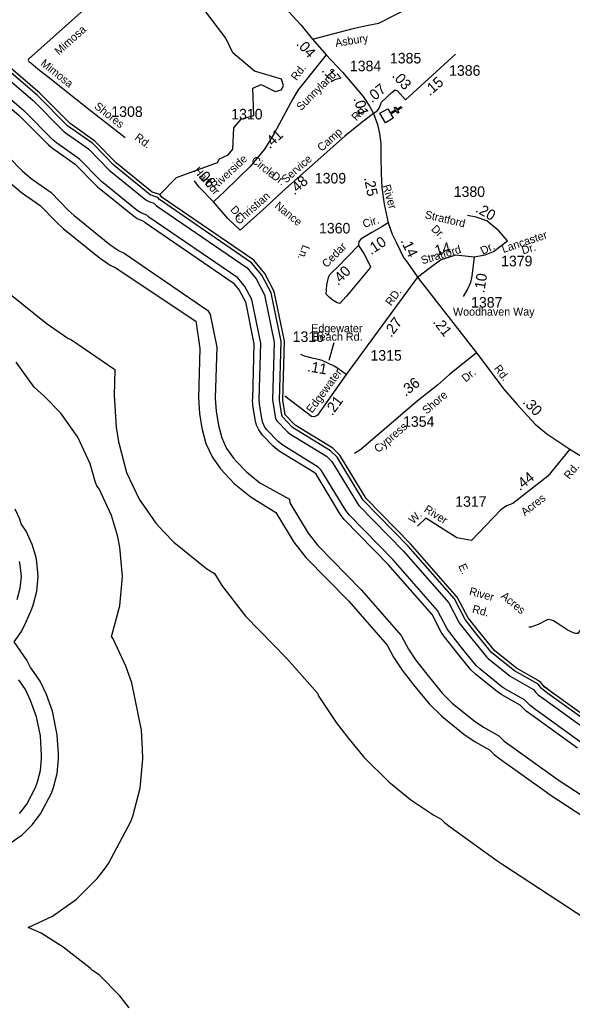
# Model space of a CAD drawing. Extents: x 2532689 to 2764727, y 536648 to 732970.
# Drawn here: x 2589422 to 2595978, y 639225 to 650929 of the extents above; entities that cross this region are included whole.
import ezdxf

# ---------------------------------------------------------------- set-up
doc = ezdxf.new("R2010")
doc.units = 0
for name, color, linetype in [('Exist Cultural Church CELL', 7, 'Continuous'), ('Exist Hydrographic Bay Label', 7, 'Continuous'), ('Exist Hydrographic Buffer Line', 7, 'Continuous'), ('Exist Hydrographic Creek Single Shore', 7, 'Continuous'), ('Exist Hydrographic River Shore', 7, 'Continuous'), ('Exist Road Primary NC Attributed', 7, 'Continuous'), ('Exist Road Primary NC Label', 7, 'Continuous'), ('Exist Road Primary NC Mileage Hundredths English Label', 7, 'Continuous'), ('Exist Road Secondary Mileage Hundredths English Label', 7, 'Continuous'), ('Exist Road Secondary Type 51 Attributed', 7, 'Continuous'), ('Exist Road Secondary Type 51 Label', 7, 'Continuous'), ('Exist Road Secondary Type 51 Number Label', 7, 'Continuous')]:
    doc.layers.add(name, color=color, linetype=linetype)

msp = doc.modelspace()

# ---------------------------------------------------------------- linework, layer by layer
at = {"layer": 'Exist Cultural Church CELL'}
msp.add_lwpolyline([(2593788, 649874), (2593816, 649824), (2593882, 649862), (2593866, 649890), (2593880, 649898), (2593896, 649870), (2593948, 649900), (2593956, 649886), (2593904, 649856), (2593920, 649828), (2593906, 649820), (2593890, 649848), (2593824, 649810), (2593853, 649760), (2593760, 649707), (2593695, 649821)], close=True, dxfattribs=at)
at = {"layer": 'Exist Hydrographic Bay Label'}
msp.add_line((2595711, 642968), (2595643, 643018), dxfattribs=at)
at = {"layer": 'Exist Hydrographic Buffer Line'}
for points in [[(2592502, 646416), (2592522, 647112), (2592404, 647691), (2592295, 647898), (2592173, 648046), (2591079, 648796), (2591061, 648821), (2590968, 648853), (2590541, 649200), (2590288, 649460), (2589990, 649670), (2589634, 650029), (2588885, 650670), (2588337, 650929), (2588091, 651115), (2587966, 651291)], [(2587714, 651088), (2587833, 650926), (2587908, 650850), (2588145, 650673), (2588207, 650635), (2588710, 650399), (2589416, 649794), (2589763, 649445), (2589812, 649404), (2590080, 649215), (2590312, 648977), (2590343, 648948), (2590767, 648605), (2590814, 648572), (2590870, 648546), (2590892, 648539), (2590909, 648523), (2591955, 647808), (2592027, 647720), (2592099, 647583), (2592201, 647084), (2592182, 646426)], [(2587898, 650973), (2587955, 650914), (2588192, 650737), (2588241, 650707), (2588754, 650467), (2589471, 649853)], [(2588842, 650602), (2589580, 649970), (2589933, 649614), (2589950, 649600), (2590236, 649398), (2590483, 649144), (2590918, 648791), (2590953, 648771), (2591012, 648752), (2591044, 648721), (2592119, 647987), (2592228, 647854), (2592327, 647664), (2592441, 647105), (2592422, 646419), (2592423, 646396), (2592451, 646223), (2592457, 646201), (2592466, 646183), (2592478, 646165), (2592602, 646036), (2592626, 646017), (2593062, 645750), (2593126, 645688), (2593428, 645188), (2593445, 645167), (2593971, 644629), (2594513, 644011), (2594636, 643776), (2594649, 643757), (2594785, 643586), (2594961, 643369), (2594979, 643351), (2595241, 643141), (2595519, 642983), (2595547, 642946), (2595572, 642921), (2595640, 642871), (2596181, 642482)], [(2596087, 642352), (2595546, 642742), (2595478, 642792), (2595411, 642860), (2595179, 642991), (2595141, 643016), (2594879, 643227), (2594838, 643268), (2594659, 643486), (2594523, 643658), (2594495, 643702), (2594380, 643920), (2593853, 644520), (2593330, 645055), (2593291, 645106), (2593000, 645587), (2592963, 645622), (2592542, 645881), (2592487, 645925), (2592355, 646063), (2592327, 646103), (2592307, 646147), (2592293, 646198), (2592265, 646371), (2592262, 646423), (2592281, 647091), (2592175, 647610), (2592094, 647765), (2592010, 647867), (2590954, 648589), (2590931, 648610), (2590898, 648621), (2590854, 648642), (2590817, 648667), (2590393, 649011), (2590369, 649033), (2590132, 649276), (2589857, 649469), (2589820, 649501), (2589471, 649853)], [(2589117, 649472), (2589451, 649135), (2589558, 649044), (2589793, 648879), (2589996, 648670), (2590066, 648607), (2590490, 648263), (2590594, 648191), (2590659, 648161), (2591655, 647480), (2591680, 647434), (2591759, 647046), (2591742, 646438), (2591752, 646287), (2591780, 646115), (2591818, 645969), (2591877, 645842), (2591957, 645728), (2591994, 645687), (2592113, 645564), (2592270, 645437)], [(2589309, 648994), (2589443, 648880), (2589663, 648726), (2589853, 648531), (2589939, 648451), (2590364, 648107), (2590494, 648018), (2590553, 647990), (2591511, 647354), (2591515, 647330), (2591559, 647029), (2591542, 646444), (2591554, 646256), (2591582, 646083), (2591630, 645901), (2591704, 645742), (2591804, 645600), (2591850, 645548), (2591969, 645425), (2592166, 645267), (2592462, 645085), (2592675, 644733), (2592816, 644551), (2593325, 644030), (2593783, 643509), (2593857, 643367), (2593959, 643211), (2594095, 643039), (2594280, 642812), (2594428, 642666), (2594690, 642455), (2594826, 642363), (2594994, 642269), (2595052, 642211), (2595120, 642161), (2595667, 641768), (2595702, 641743), (2596950, 640926)], [(2589310, 647675), (2589734, 647331), (2589994, 647152), (2590037, 647132), (2590551, 646781), (2590542, 646473), (2590567, 646096), (2590595, 645923), (2590600, 645895), (2590690, 645558), (2590838, 645242), (2591038, 644957), (2591131, 644853), (2591250, 644730), (2591643, 644414), (2591732, 644360), (2591819, 644216), (2592100, 643852), (2592591, 643351), (2592953, 642939), (2592972, 642902), (2593175, 642590), (2593311, 642419), (2593330, 642395), (2593506, 642180), (2593801, 641886), (2594063, 641676), (2594337, 641491), (2594423, 641443), (2594462, 641404), (2594530, 641354), (2595083, 640956), (2595154, 640907), (2596356, 640119)], [(2590722, 639205), (2590611, 639350), (2590364, 639596), (2590285, 639651), (2590256, 639679), (2589936, 639928), (2589675, 640092), (2589521, 640160), (2589809, 640294), (2590094, 640494), (2590341, 640740), (2590428, 640852), (2590477, 640920), (2590739, 641416), (2590763, 641482), (2590851, 641813), (2590882, 642160), (2590878, 642275), (2590865, 642501), (2590751, 643063), (2590680, 643261), (2590530, 643584), (2590509, 643612), (2590520, 643640), (2590610, 643976), (2590641, 644324), (2590610, 644671), (2590590, 644773), (2590581, 644812), (2590511, 645047), (2590364, 645363), (2590338, 645399), (2590319, 645440), (2590257, 645660), (2590110, 645976), (2589910, 646262), (2589713, 646465), (2589595, 646572), (2589380, 646868)], [(2596041, 642287), (2595498, 642678), (2595430, 642727), (2595359, 642798), (2595140, 642921), (2595091, 642954), (2594829, 643164), (2594776, 643217), (2594596, 643437), (2594460, 643608), (2594424, 643665), (2594314, 643874), (2593794, 644466), (2593273, 644999), (2593223, 645064), (2592937, 645537), (2592914, 645559), (2592500, 645812), (2592430, 645869), (2592311, 645992), (2592294, 646011), (2592258, 646063), (2592231, 646119), (2592214, 646185), (2592186, 646358), (2592182, 646426)], [(2596228, 642547), (2595687, 642936), (2595611, 642994), (2595573, 643045), (2595291, 643203), (2595024, 643420), (2594847, 643635), (2594707, 643813), (2594579, 644057), (2594029, 644683), (2593496, 645230), (2593189, 645738), (2593111, 645813), (2592660, 646091), (2592539, 646217), (2592530, 646236), (2592502, 646416)], [(2592270, 645437), (2592622, 645241), (2592627, 645199), (2592846, 644837), (2592959, 644691), (2593472, 644166), (2593949, 643623), (2594035, 643460), (2594116, 643335), (2594251, 643164), (2594435, 642939), (2594553, 642821), (2594815, 642611), (2594924, 642537), (2595108, 642434), (2595171, 642372), (2595238, 642323), (2595783, 641930), (2595812, 641911), (2597068, 641087)], [(2589357, 643548), (2589443, 643670), (2589500, 643786), (2589564, 643939), (2589580, 643982), (2589625, 644150), (2589641, 644324), (2589625, 644497), (2589615, 644548), (2589606, 644587), (2589571, 644705), (2589498, 644863), (2589439, 644947), (2589423, 645004), (2589369, 645121)], [(2589392, 644050), (2589428, 644185), (2589441, 644324), (2589428, 644463), (2589420, 644503)], [(2589309, 641160), (2589451, 641260), (2589575, 641383), (2589618, 641439), (2589667, 641507), (2589798, 641755), (2589822, 641821), (2589866, 641986), (2589882, 642160), (2589880, 642218), (2589867, 642444), (2589810, 642725), (2589739, 642922), (2589664, 643084), (2589564, 643226), (2589549, 643245), (2589537, 643266), (2589506, 643331), (2589357, 643548)], [(2589421, 641512), (2589456, 641556), (2589505, 641624), (2589610, 641822), (2589634, 641889), (2589669, 642021), (2589682, 642160), (2589680, 642206), (2589667, 642432), (2589621, 642657), (2589550, 642854), (2589490, 642984), (2589410, 643098)]]:
    msp.add_lwpolyline(points, dxfattribs=at)
at = {"layer": 'Exist Hydrographic Creek Single Shore'}
for points in [[(2591794, 649278), (2591893, 649328), (2591950, 649395), (2591961, 649645), (2592051, 649748), (2592201, 649793), (2592186, 650118), (2592285, 650161), (2592454, 650079), (2592528, 650099), (2592552, 650149), (2592526, 650223), (2592207, 650319), (2591952, 650538), (2591866, 650712), (2591593, 651072)], [(2591085, 648855), (2591282, 649057), (2591770, 649234), (2591794, 649278)]]:
    msp.add_lwpolyline(points, dxfattribs=at)
at = {"layer": 'Exist Hydrographic River Shore'}
for points in [[(2591085, 648855), (2590994, 648884), (2590570, 649228), (2590314, 649490), (2590019, 649698), (2589662, 650058), (2588907, 650704), (2588361, 650961), (2588124, 651138), (2588004, 651301), (2587976, 651412)], [(2595316, 643235), (2595054, 643445), (2594879, 643660), (2594743, 643832), (2594613, 644079), (2594059, 644710), (2593531, 645251), (2593221, 645763), (2593136, 645845), (2592689, 646119), (2592570, 646243), (2592542, 646415), (2592562, 647115), (2592442, 647705), (2592329, 647920), (2592201, 648076), (2591112, 648820), (2591085, 648855)], [(2595644, 643016), (2595600, 643075), (2595316, 643235)], [(2598079, 641235), (2597977, 641307), (2597764, 641551), (2597543, 641732), (2596251, 642580), (2595644, 643016)]]:
    msp.add_lwpolyline(points, dxfattribs=at)
at = {"layer": 'Exist Road Primary NC Attributed'}
for p, q in [((2592894, 650698), (2593056, 650514)), ((2594154, 647860), (2594841, 646976))]:
    msp.add_line(p, q, dxfattribs=at)
for points in [[(2591662, 652344), (2591728, 652247), (2592136, 651601), (2592224, 651499), (2592384, 651278), (2592757, 650867), (2592894, 650698)], [(2593056, 650514), (2593250, 650307), (2593495, 650017), (2593573, 649904), (2593621, 649817)], [(2593621, 649817), (2593666, 649686), (2593691, 649579), (2593705, 649461), (2593705, 649301), (2593709, 649106), (2593719, 648938), (2593745, 648741), (2593792, 648520)], [(2593792, 648520), (2593840, 648384), (2593889, 648290), (2593977, 648110), (2594019, 648054), (2594154, 647860)], [(2594841, 646976), (2595167, 646548), (2595322, 646363), (2595537, 646131), (2595677, 646018), (2595949, 645835)], [(2595949, 645835), (2596168, 645700), (2596719, 645439)]]:
    msp.add_lwpolyline(points, dxfattribs=at)
at = {"layer": 'Exist Road Secondary Type 51 Attributed'}
msp.add_line((2594142, 647875), (2593295, 646719), dxfattribs=at)
for points in [[(2591662, 652344), (2591603, 652303), (2591414, 652127), (2590696, 651511), (2589526, 650460), (2589521, 650450), (2589529, 650433), (2589553, 650419), (2589635, 650347), (2589761, 650253), (2590242, 649868), (2590671, 649531)], [(2592894, 650698), (2593392, 650829), (2593536, 650862), (2593682, 650888), (2594055, 651077), (2594102, 651118), (2594142, 651139), (2594179, 651167), (2594434, 651422), (2594568, 651513), (2594701, 651579), (2594799, 651594), (2594823, 651594), (2595138, 651669), (2595141, 651670), (2595535, 651771)], [(2593056, 650514), (2592724, 650099), (2592663, 649990), (2592440, 649580), (2592326, 649394), (2592155, 649187), (2591856, 648897), (2591719, 648768)], [(2593998, 649979), (2594592, 650520)], [(2593621, 649817), (2593665, 649852), (2593685, 649879), (2593713, 649952), (2593839, 650072), (2593878, 650097)], [(2593878, 650097), (2593902, 650084), (2593998, 649979)], [(2593621, 649817), (2593464, 649699), (2593281, 649548), (2592541, 648891), (2592351, 648715), (2592036, 648433), (2591890, 648572), (2591719, 648768)], [(2591719, 648768), (2591548, 648947), (2591495, 649017)], [(2595210, 648306), (2595105, 648426), (2594963, 648543), (2594837, 648589), (2594733, 648607)], [(2593792, 648520), (2593717, 648473), (2593599, 648406), (2593471, 648330), (2593445, 648298), (2593441, 648250)], [(2593086, 647872), (2593103, 647908), (2593126, 647932), (2593192, 647993), (2593441, 648250)], [(2593441, 648250), (2593472, 648205), (2593505, 648154), (2593583, 648002), (2593575, 647980), (2593299, 647649), (2593252, 647597)], [(2594814, 648116), (2594943, 648142), (2595044, 648181), (2595210, 648306)], [(2594142, 647875), (2594275, 647979), (2594415, 648079), (2594597, 648141), (2594814, 648116)], [(2594814, 648116), (2594787, 647889), (2594770, 647813), (2594733, 647731), (2594683, 647646)], [(2593252, 647597), (2593218, 647561), (2593189, 647570), (2593142, 647597), (2593094, 647636), (2593059, 647675), (2593066, 647785), (2593086, 647872)], [(2593295, 646719), (2593253, 646751), (2593184, 646800), (2593152, 646820), (2593009, 646886), (2592967, 646898), (2592908, 646912), (2592802, 646938), (2592757, 646956)], [(2594841, 646976), (2594522, 646720), (2594379, 646593), (2594138, 646404), (2593467, 645829), (2593392, 645784)], [(2593295, 646719), (2592954, 646237), (2592921, 646219), (2592882, 646224), (2592569, 646464)], [(2595949, 645835), (2595688, 645514), (2595272, 645188), (2595198, 645163), (2595129, 645116), (2594782, 644749), (2594606, 644783), (2594239, 645016), (2594141, 644921)], [(2597152, 645224), (2596043, 643647), (2596016, 643648), (2596001, 643652), (2595955, 643671), (2595916, 643690), (2595800, 643772), (2595754, 643797), (2595732, 643806), (2595714, 643810), (2595696, 643813), (2595681, 643811), (2595573, 643753), (2595485, 643723), (2595463, 643723)]]:
    msp.add_lwpolyline(points, dxfattribs=at)
at = {"layer": 'Exist Road Secondary Type 51 Label'}
msp.add_lwpolyline([(2593148, 647097), (2593089, 646885)], dxfattribs=at)

# ---------------------------------------------------------------- texts
at = {"layer": 'Exist Road Primary NC Label'}
for s, rotation, p in [('River', 285.9555, (2593726, 648960)), ('Rd.', 307.3351, (2595044, 646791))]:
    msp.add_text(s, height=95, rotation=rotation, dxfattribs=at).set_placement(p)
at = {"layer": 'Exist Road Primary NC Mileage Hundredths English Label'}
for s, rotation, p in [('.04', 312.5048, (2592696, 650637)), ('.17', 311.5576, (2592999, 650323)), ('.01', 287.6062, (2593379, 649994)), ('.25', 280.9461, (2593506, 649054)), ('.14', 295.9471, (2593938, 648307)), ('.21', 307.8493, (2594319, 647342)), ('.30', 312.8646, (2595383, 646388))]:
    msp.add_text(s, height=125, rotation=rotation, dxfattribs=at).set_placement(p)
at = {"layer": 'Exist Road Secondary Mileage Hundredths English Label'}
for s, rotation, p in [('.03', 311.9245, (2593832, 650259)), ('.15', 41.3329, (2594287, 650018)), ('.07', 39.8333, (2593601, 649937)), ('.41', 43.1795, (2592388, 649392)), ('.06', 310.929, (2591513, 649101)), ('.48', 41.5464, (2592680, 648844)), ('.20', 330.3956, (2594820, 648655)), ('.10', 33.8311, (2593590, 648135)), ('.14', 15.0084, (2594320, 648114)), ('.40', 45.845, (2593198, 647769)), ('.10', 81.1366, (2594933, 647681)), ('.27', 53.4536, (2593829, 647153)), ('.11', 350.301, (2592828, 646759)), ('.36', 38.0445, (2593999, 646455)), ('.21', 53.6098, (2593129, 646224)), ('.44', 37.9803, (2595356, 645335))]:
    msp.add_text(s, height=125, rotation=rotation, dxfattribs=at).set_placement(p)
at = {"layer": 'Exist Road Secondary Type 51 Label'}
for s, rotation, p in [('Mimosa', 41.9422, (2589887, 650504)), ('Asbury', 9.3815, (2593172, 650606)), ('Mimosa', 321.3985, (2589661, 650396)), ('Rd.', 53.3946, (2592707, 650200)), ('Sunnyland', 44.9664, (2592760, 649844)), ('Shores', 321.7534, (2590299, 649886)), ('Rd.', 48.0894, (2593418, 649722)), ('Camp', 41.6064, (2593004, 649360)), ('Rd.', 324.0272, (2590778, 649514)), ('Riverside', 43.2395, (2591744, 648906)), ('Circle', 321.0893, (2592161, 649248)), ('Service', 41.6064, (2592581, 648984)), ('Harbor', 310.989, (2591480, 649135)), ('Dr.', 323.1331, (2592399, 649059)), ('Christian', 41.2626, (2592024, 648494)), ('Dr.', 313.1158, (2591913, 648670)), ('Nance', 320.8904, (2592439, 648707)), ('Stratford', 346.8083, (2594222, 648576)), ('Cir.', 16.9783, (2593507, 648459)), ('Dr.', 316.2577, (2594296, 648437)), ('Lancaster', 18.5859, (2595160, 648161)), ('Ln.', 248.6694, (2592782, 648266)), ('Cedar', 45.905, (2593065, 647981)), ('Stratford', 16.58, (2594199, 648027)), ('Dr.', 26.4874, (2594917, 648139)), ('Dr.', 16.4767, (2595393, 648145)), ('RD.', 53.5136, (2593828, 647527)), ('Woodhaven Way', 0.1121, (2594563, 647418)), ('Edgewater', 53.6698, (2592890, 646255)), ('Dr.', 38.7736, (2594712, 646624)), ('Shore', 40.6079, (2594248, 646243)), ('Cypress', 40.6079, (2593676, 645786)), ('Rd.', 50.8789, (2595943, 645470)), ('Acres', 38.0403, (2595415, 645037)), ('River', 327.5587, (2594210, 645099)), ('W.', 44.1093, (2594091, 644941)), ('E.', 295.0882, (2594623, 644449)), ('River', 345.3126, (2594748, 644107)), ('Acres', 319.9487, (2595123, 644079)), ('Rd.', 345.3126, (2594784, 643897))]:
    msp.add_text(s, height=95, rotation=rotation, dxfattribs=at).set_placement(p)
for s, p in [('Edgewater', (2592880, 647222)), ('Beach Rd.', (2592896, 647122))]:
    msp.add_text(s, height=95, dxfattribs=at).set_placement(p)
at = {"layer": 'Exist Road Secondary Type 51 Number Label'}
for s, p in [('1385', (2593814, 650411)), ('1384', (2593339, 650319)), ('1386', (2594516, 650265)), ('1308', (2590509, 649777)), ('1310', (2591931, 649747)), ('1309', (2592923, 648987)), ('1380', (2594571, 648828)), ('1360', (2592973, 648394)), ('1379', (2595133, 648005)), ('1387', (2594777, 647514)), ('1316', (2592660, 647107)), ('1315', (2593583, 646885)), ('1354', (2593970, 646100)), ('1317', (2594589, 645151))]:
    msp.add_text(s, height=125, rotation=359.94, dxfattribs=at).set_placement(p)

doc.saveas('drawing.dxf')
